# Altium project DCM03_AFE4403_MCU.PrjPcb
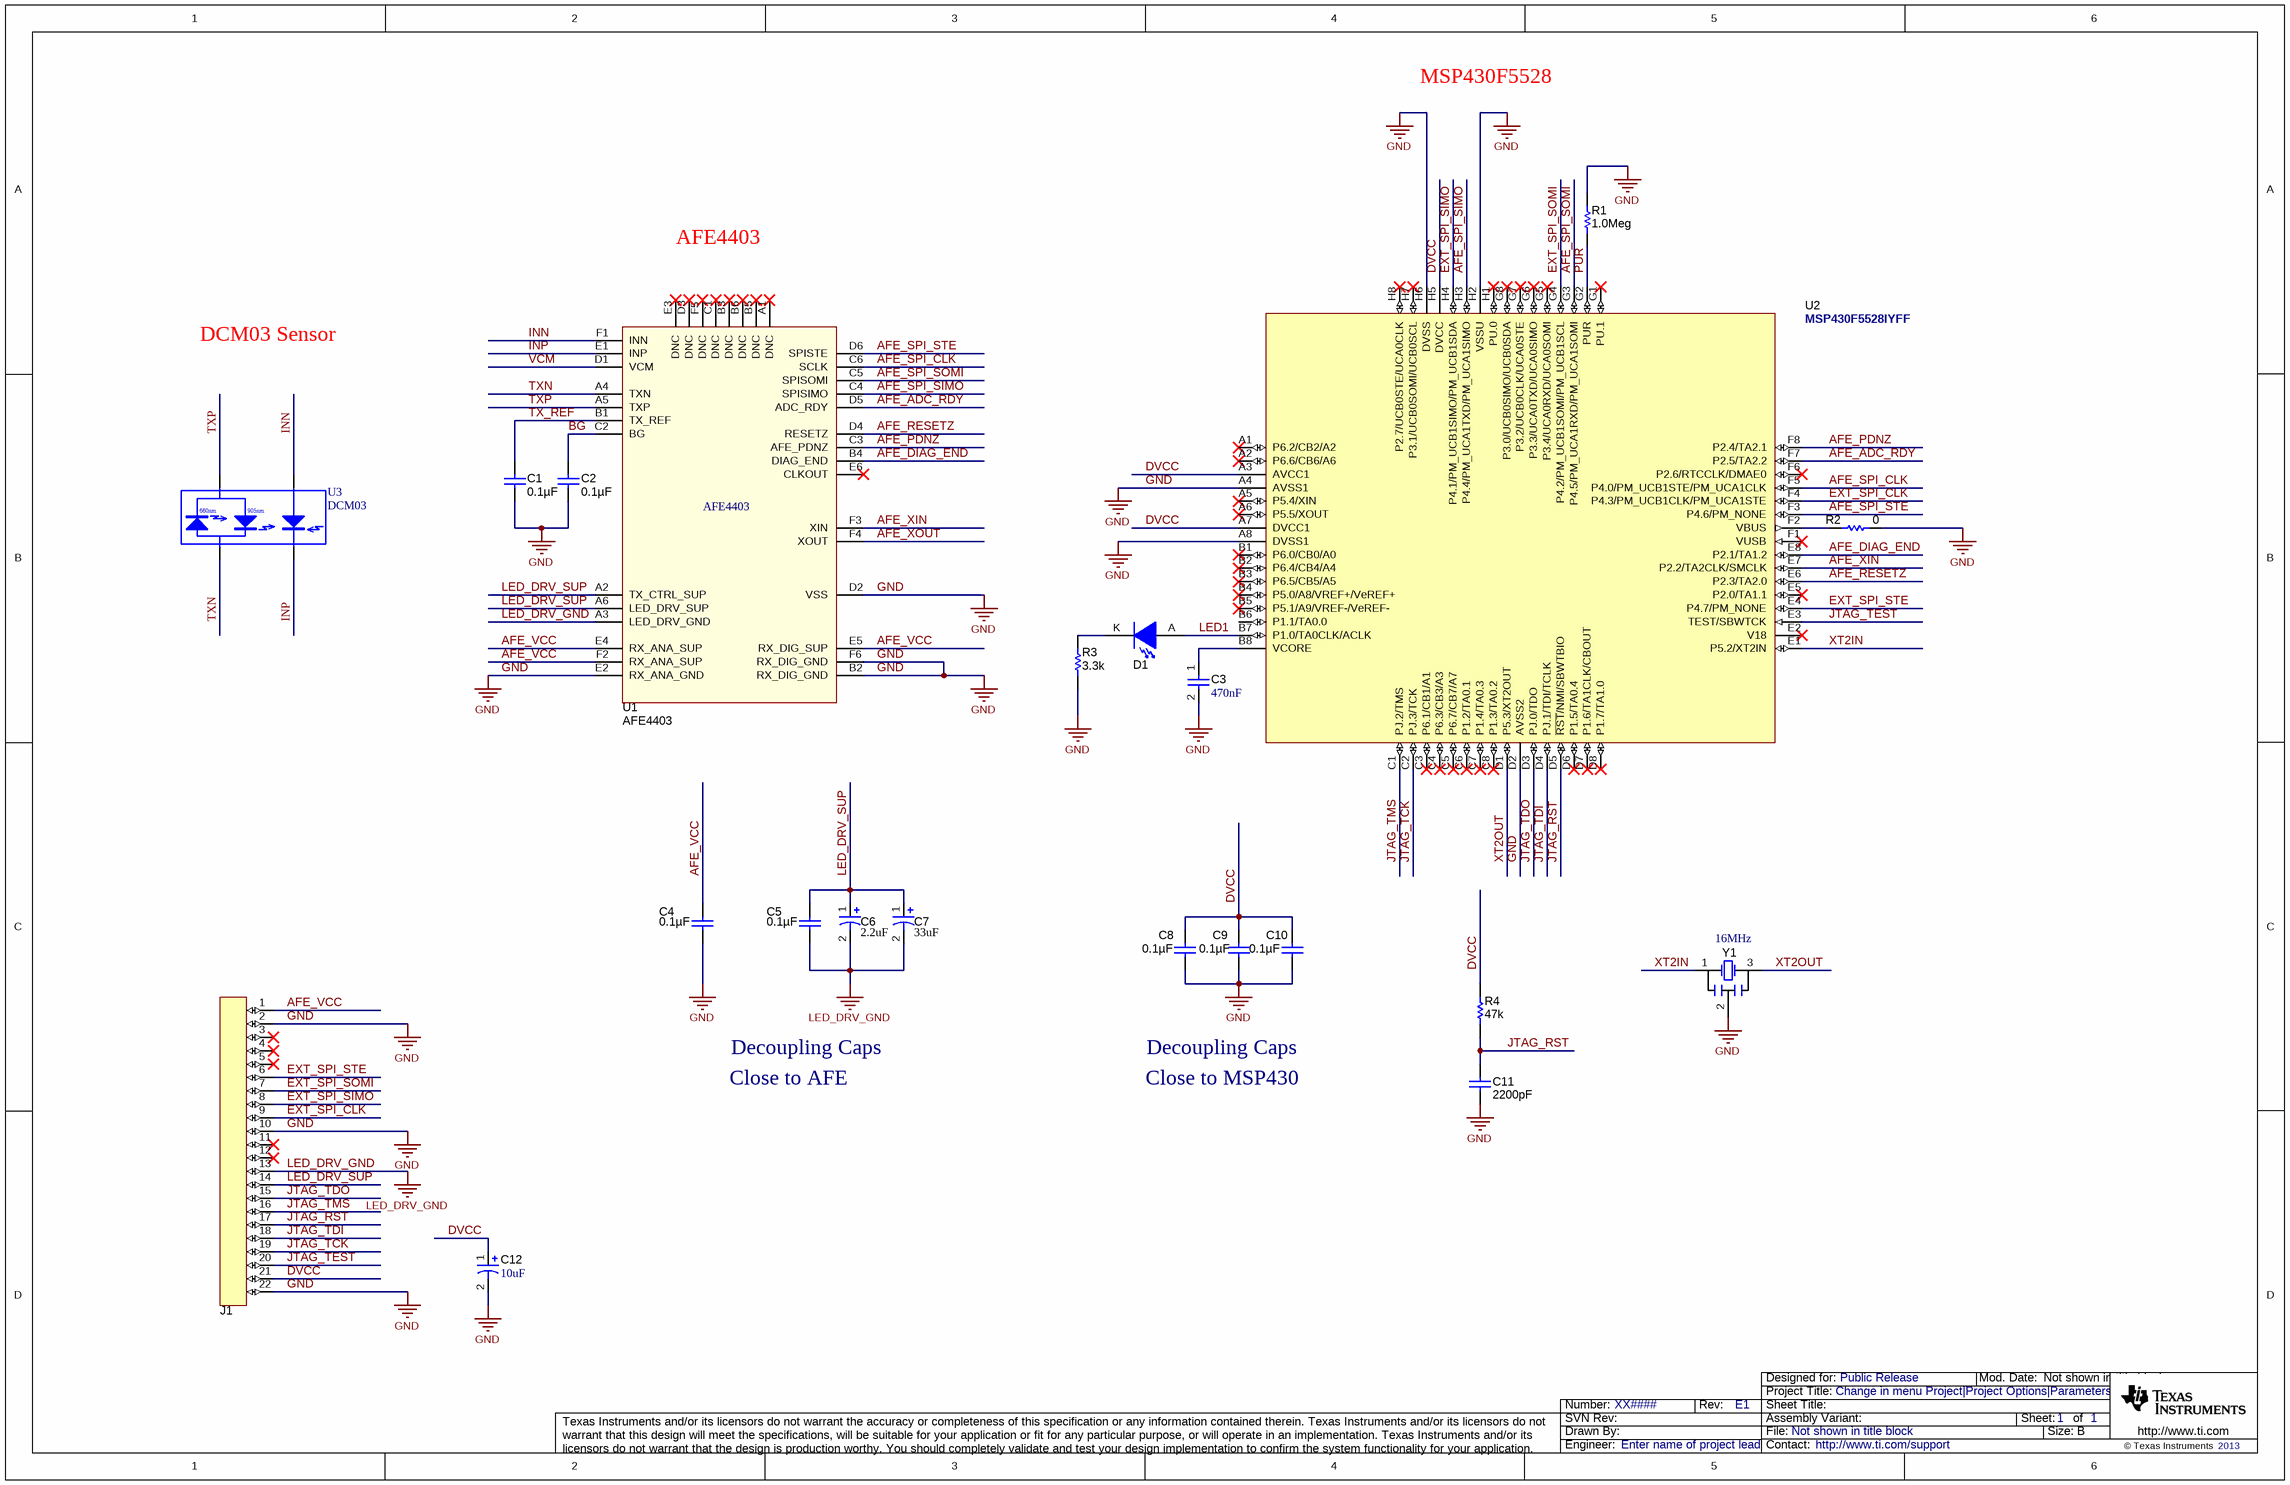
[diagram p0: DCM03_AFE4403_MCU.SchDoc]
CopyrightYear: 2013; PCB_Layout: Who did the Layout?; PCB_Rev: E1; PRJ_Customer: Public Release; PRJ_Engineer: Enter name of project lead; PRJ_Number: XX####; PRJ_Title: Change in menu Project|Project Options|Parameters; SCH_Rev: E1; TechSupport: http://www.ti.com/support
1 sheet, 22 parts. Net scope: global (net labels, ports and power ports of the same name join across sheets).
Board file: DCM03_AFE4403_MCU.PcbDoc

## Sheet DCM03_AFE4403_MCU.SchDoc
size 431 x 279 mm; Date: Not shown in title block; ApprovedBy: Not shown in title block; CheckedBy: Not shown in title block; Author: Not shown in title block; CompanyName: Not shown in title block; Engineer: Not shown in title block; Organization: Not shown in title block; Address1: Not shown in title block; Address2: Not shown in title block; Address3: Not shown in title block; Address4: Not shown in title block; DocumentNumber: 1; Revision: Use project parameter SCH_Rev; SheetNumber: 1; SheetTotal: 1; PageSetup: Record=PageOptions|CenterHorizontal=True|CenterVertical=True|PrintScale=1.00|XCorrection=1.00|YCorrection=1.00|PrintKind=0|BorderSize=5000000|LeftOffset=0|BottomOffset=0|Orientation=2|PaperLength=1000|PaperWidth=1000|Scale=100|PaperSource=15|PrintQuality=600|MediaType=1|DitherType=10|PaperKind=Letter|PrintScaleMode=1

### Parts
C1  ValueDisplayed: 0.1µF  [0201]  (hidden comment: CL03A104KP3NNNC)
C2  ValueDisplayed: 0.1µF  [0201]  (hidden comment: CL03A104KP3NNNC)
C3  value 470nF  [0402]  (hidden comment: C1005X5R1C474K)
C4  ValueDisplayed: 0.1µF  [0201]  (hidden comment: CL03A104KP3NNNC)
C5  ValueDisplayed: 0.1µF  [0201]  (hidden comment: CL03A104KP3NNNC)
C6  value 2.2uF  [C0603_POL]  (hidden comment: TCM1A225M8R)
C7  value 33uF  [C0603_POL]  (hidden comment: TR8M336M6R3C1500)
C8  ValueDisplayed: 0.1µF  [0201]  (hidden comment: CL03A104KP3NNNC)
C9  ValueDisplayed: 0.1µF  [0201]  (hidden comment: CL03A104KP3NNNC)
C10  ValueDisplayed: 0.1µF  [0201]  (hidden comment: CL03A104KP3NNNC)
C11  ValueDisplayed: 2200pF  [0201]  (hidden comment: GRM033R61A222KA01D)
C12  value 10uF  [C0603_POL1]  (hidden comment: F980J106MMA)
D1  (no value)  [LED_0402]
J1  22pin SPO2 Module Connector  [CONN-22PADS]  (value not drawn)
R1  value 1.0Meg  [R0402]  (hidden comment: CRCW04021M00JNED)
R2  value 0  [R0201]  (hidden comment: ERJ-1GE0R00C)
R3  value 3.3k  [R0201]  (hidden comment: RC0603F332CS)
R4  value 47k  [R0201]  (hidden comment: RC0603F473CS)
U1  AFE4403  [BGA36C50P6X6_304X304X50]
U2  value MSP430F5528IYFF  [YFF-64]
U3  DCM03  [DCM03]
Y1  value 16MHz  [RESONATOR-1.3X3.2-MURATA]

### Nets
GND: C1.2 C2.2 C3.2 C4.2 C8.2 C9.2 C10.2 C11.2 C12.2(-) J1.2 J1.10 J1.22 R1.1 R2.2 R3.1 U1.B2(RX_DIG_GND) U1.D2(VSS) U1.E2(RX_ANA_GND) U1.F6(RX_DIG_GND) U2.A4(AVSS1) U2.A8(DVSS1) U2.D2(AVSS2) U2.H2(VSSU) U2.H6(DVSS) Y1.2
LED_DRV_GND: C5.2 C6.2(-) C7.2(-) J1.13 U1.A3(LED_DRV_GND)
AFE_ADC_RDY: U1.D5(ADC_RDY) U2.F7(P2.5/TA2.2)
AFE_DIAG_END: U1.B4(DIAG_END) U2.E8(P2.1/TA1.2)
AFE_PDNZ: U1.C3(AFE_PDNZ) U2.F8(P2.4/TA2.1)
AFE_RESETZ: U1.D4(RESETZ) U2.E6(P2.3/TA2.0)
AFE_SPI_CLK: U1.C6(SCLK) U2.F5(P4.0/PM_UCB1STE/PM_UCA1CLK)
AFE_SPI_SIMO: U1.C4(SPISIMO) U2.H3(P4.4/PM_UCA1TXD/PM_UCA1SIMO)
AFE_SPI_SOMI: U1.C5(SPISOMI) U2.G3(P4.5/PM_UCA1RXD/PM_UCA1SOMI)
AFE_SPI_STE: U1.D6(SPISTE) U2.F3(P4.6/PM_NONE)
AFE_VCC: C4.1 J1.1 U1.E4(RX_ANA_SUP) U1.E5(RX_DIG_SUP) U1.F2(RX_ANA_SUP)
AFE_XIN: U1.F3(XIN) U2.E7(P2.2/TA2CLK/SMCLK)
AFE_XOUT: U1.F4(XOUT)
BG: C2.1 U1.C2(BG)
DVCC: C8.1 C9.1 C10.1 C12.1(+) J1.21 R4.2 U2.A3(AVCC1) U2.A7(DVCC1) U2.H5(DVCC)
EXT_SPI_CLK: J1.9 U2.F4(P4.3/PM_UCB1CLK/PM_UCA1STE)
EXT_SPI_SIMO: J1.8 U2.H4(P4.1/PM_UCB1SIMO/PM_UCB1SDA)
EXT_SPI_SOMI: J1.7 U2.G4(P4.2/PM_UCB1SOMI/PM_UCB1SCL)
EXT_SPI_STE: J1.6 U2.E4(P4.7/PM_NONE)
INN: U1.F1(INN) U3.4(A)
INP: U1.E1(INP) U3.3(K)
JTAG_RST: C11.1 J1.17 R4.1 U2.D5(~{RST}/NMI/SBWTBIO)
JTAG_TCK: J1.19 U2.C2(PJ.3/TCK)
JTAG_TDI: J1.18 U2.D4(PJ.1/TDI/TCLK)
JTAG_TDO: J1.15 U2.D3(PJ.0/TDO)
JTAG_TEST: J1.20 U2.E3(TEST/SBWTCK)
JTAG_TMS: J1.16 U2.C1(PJ.2/TMS)
LED1: D1.A U2.B7(P1.0/TA0CLK/ACLK)
LED_DRV_SUP: C5.1 C6.1(+) C7.1(+) J1.14 U1.A2(TX_CTRL_SUP) U1.A6(LED_DRV_SUP)
PUR: R1.2 U2.G2(PUR)
TX_REF: C1.1 U1.B1(TX_REF)
TXN: U1.A4(TXN) U3.1(A-K)
TXP: U1.A5(TXP) U3.2(A-K)
VCM: U1.D1(VCM)
XT2IN: U2.E1(P5.2/XT2IN) Y1.1
XT2OUT: U2.D1(P5.3/XT2OUT) Y1.3
NetC3_1: C3.1 U2.B8(VCORE)
NetD1_K: D1.K R3.2
NetR2_1: R2.1 U2.F2(VBUS)

Not connected (* = marked no-connect by the designer): J1 3* 4* 5* 11* 12*; U1 A1(DNC)* B3(DNC)* B5(DNC)* B6(DNC)* C1(DNC)* D3(DNC)* E3(DNC)* E6(CLKOUT)* F5(DNC)*; U2 A1(P6.2/CB2/A2)* A2(P6.6/CB6/A6)* A5(P5.4/XIN)* A6(P5.5/XOUT)* B1(P6.0/CB0/A0)* B2(P6.4/CB4/A4)* B3(P6.5/CB5/A5)* B4(P5.0/A8/VREF+/VeREF+)* B5(P5.1/A9/VREF-/VeREF-)* B6(P1.1/TA0.0) C3(P6.1/CB1/A1)* C4(P6.3/CB3/A3)* C5(P6.7/CB7/A7)* C6(P1.2/TA0.1)* C7(P1.4/TA0.3)* C8(P1.3/TA0.2)* D6(P1.5/TA0.4)* D7(P1.6/TA1CLK/CBOUT)* D8(P1.7/TA1.0)* E2(V18)* E5(P2.0/TA1.1)* F1(VUSB)* F6(P2.6/RTCCLK/DMAE0)* G1(PU.1)* G5(P3.4/UCA0RXD/UCA0SOMI)* G6(P3.3/UCA0TXD/UCA0SIMO)* G7(P3.2/UCB0CLK/UCA0STE)* G8(P3.0/UCB0SIMO/UCB0SDA)* H1(PU.0)* H7(P3.1/UCB0SOMI/UCB0SCL)* H8(P2.7/UCB0STE/UCA0CLK)*

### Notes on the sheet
- MSP430F5528
- AFE4403
- DCM03 Sensor
- Close to AFE
- Decoupling Caps
- Close to MSP430

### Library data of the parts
C1 C2 C4 C5 C8-C10 = CL03A104KP3NNNC: CAP, CERM, 0.1uF, 10V, +/-10%, X5R, 0201; Manufacturer: Samsung; Polarized: N; CompType: Capacitor; U/M: EA; Cap_F: 0.0000001; Tolerance_%: 10; Value1: Unknown; TaMin_C: -55; TaMax_C: 85
C3 = C1005X5R1C474K: CAP, CERAMIC, 470nF, 10%, 16V, X5R, 0402; MANUFACTURER: TDK; POPULATE: Y; CONSIGNED: N
C6 = TCM1A225M8R: CAP, TANTALUM, 2.2uF, 20%, 10V, 0603; MANUFACTURER: ROHM SEMICONDCTOR; POPULATE: Y; CONSIGNED: N
C7 = F980J106MMA: CAP,TANTALUM, 33uF, 20%, 6.3V, 1.5 OHM, 0603; MANUFACTURER: Vishay Sprague; POPULATE: Y; CONSIGNED: N
C11 = GRM033R61A222KA01D: CAP, CERM, 2200pF, 10V, +/-10%, X5R, 0201; Manufacturer: MuRata; Polarized: N; CompType: Capacitor; U/M: EA; Cap_F: 0.0000000022; Tolerance_%: 10; Value1: Unknown; TaMin_C: -55; TaMax_C: 85
C12 = F980J106MMA: CAP,TANTALUM, 10UF, 20%, 6.3V, 6 OHM, SMT0603; MANUFACTURER: NICHICON; POPULATE: Y; CONSIGNED: N
D1 = APHHS1005CGCK: LED, GREEN, SMT0402; MANUFACTURER: KINGBRIGHT; POPULATE: Y; CONSIGNED: N
J1 = Conn-22pin-PadsOnly: 22pin SPO2 Module Connector pads; Manufacturer: Used in BOM report; SymbolVersion: use current date i.e. 2008-05-20; SymbolCreator: Use a-id; CompType: Used in some BOM reports.  Useful for finding later.; U/M: EA, IN, or GM
R1 = CRCW04021M00JNED: RES, 1.0Meg ohm, 5%, 0.063W, 0402; Manufacturer: Vishay-Dale; CompType: Resistor; Res_ohm: 1000000; Value_Code: 1M00; Tolerance_%: 5; Power_W: 0.063; VDC_V: 50; TempCo: 200 ppm/C; EIA_Code: E24; U/M: EA
R2 = ERJ-1GE0R00C: RES, 0 ohm, 5%, 0.05W, 0201; Manufacturer: Panasonic; CompType: Resistor; Value_Code: 0000; Tolerance_%: 5; Power_W: 0.05; VDC_V: 15; TempCo: 600 ppm/C; EIA_Code: E24; U/M: EA
R3 = ERJ-1GEF49R9C: RES, 3.3k ohm, 1%, 0.05W, 0201; Manufacturer: Samsung Electro-Mechanics America, Inc; CompType: Resistor; Value_Code: 3k30; Tolerance_%: 1; Power_W: 0.05; VDC_V: 25; TempCo: 100 ppm/C; EIA_Code: E96; U/M: EA
R4 = ERJ-1GEF49R9C: RES, 47k ohm, 1%, 0.05W, 0201; Manufacturer: Samsung Electro-Mechanics America, Inc; CompType: Resistor; Value_Code: 47k0; Tolerance_%: 1; Power_W: 0.05; VDC_V: 25; TempCo: 100 ppm/C; EIA_Code: E96; U/M: EA
U1 = AFE4403: BGA, 36 PINS; Manufacturer: TEXAS INSTRUMENTS
U2 = MSP430F5528IYFFR: IC, MIXED SIGNAL MICROCONTROLLER, BGA-64; MANUFACTURER: TEXAS INSTRUMENTS; POPULATE: Y
U3 = DCM03: Integrated Dual Emitter and Photodetector; Manufacturer: APMKorea; U/M: EA
Y1 = CSTCE8M00G55-R0: CRYSTAL, PIEZO CERAMIC RESONATOR, 16.00 MHz, SMD, 0.5%, 15pF, SMD; MANUFACTURER: MURATA; PART NUMBER: CSTCE16M0V53-R0; POPULATE: Y; CONSIGNED: N

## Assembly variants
001: not fitted FID1 FID2 FID3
